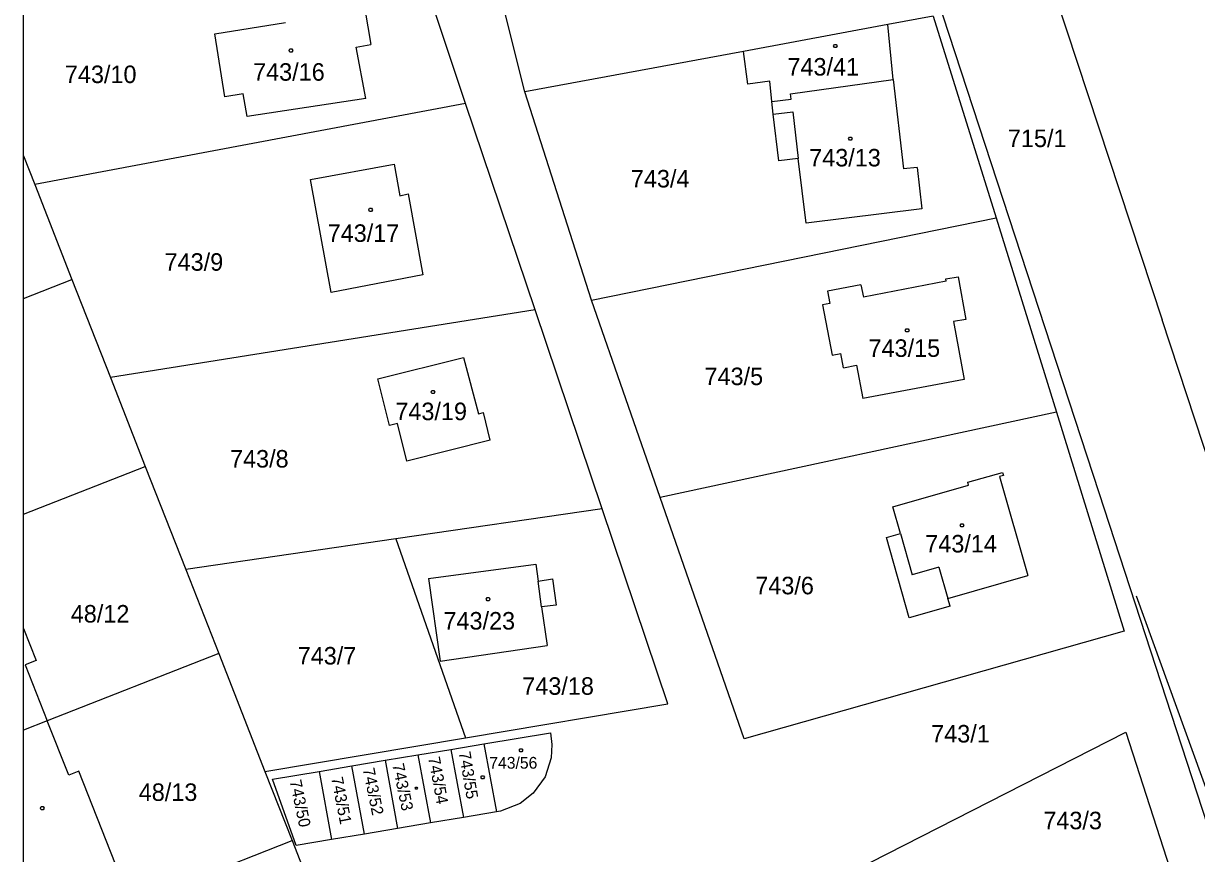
# Model space of a CAD drawing. Extents: x -639590 to -639298, y -1193269 to -1192863.
# Drawn here: x -639590.4 to -639476.5, y -1193132.4 to -1193051.8 of the extents above; entities that cross this region are included whole.
import ezdxf

# ---------------------------------------------------------------- set-up
doc = ezdxf.new("R2010")
doc.units = 0
for name, color, linetype in [('Vrstva 1', 7, 'Continuous'), ('Vrstva 2', 7, 'Continuous'), ('Vrstva 22', 7, 'Continuous'), ('Vrstva 4', 7, 'Continuous'), ('Vrstva 5', 7, 'Continuous'), ('Vrstva 61', 7, 'Continuous')]:
    doc.layers.add(name, color=color, linetype=linetype)

msp = doc.modelspace()

# ---------------------------------------------------------------- linework, layer by layer
at = {"layer": 'Vrstva 1'}
for p, q in [((-639506.87, -1193033.57), (-639486.01, -1193097.33)), ((-639547.47, -1193059.58), (-639554.02, -1193040.01)), ((-639541.72, -1193058.45), (-639545.4, -1193043.83)), ((-639492.18, -1193043.2), (-639479.86, -1193080.55)), ((-639557.26, -1193050.41), (-639556.66, -1193053.85)), ((-639571.83, -1193052.82), (-639564.97, -1193051.71)), ((-639506.48, -1193051.9), (-639520.51, -1193054.51)), ((-639502.09, -1193051.09), (-639506.48, -1193051.9)), ((-639505.97, -1193057.23), (-639506.48, -1193051.9)), ((-639502.09, -1193051.09), (-639495.98, -1193070.66)), ((-639570.85, -1193058.91), (-639571.83, -1193052.82)), ((-639558.11, -1193054.1), (-639556.66, -1193053.85)), ((-639557.17, -1193059.07), (-639558.11, -1193054.1)), ((-639520.51, -1193054.51), (-639541.72, -1193058.45)), ((-639520.08, -1193057.71), (-639520.51, -1193054.51)), ((-639517.95, -1193057.42), (-639520.08, -1193057.71)), ((-639517.76, -1193059.39), (-639517.95, -1193057.42)), ((-639515.93, -1193058.62), (-639505.97, -1193057.23)), ((-639505.97, -1193057.23), (-639504.97, -1193065.92)), ((-639569.05, -1193058.62), (-639570.85, -1193058.91)), ((-639568.69, -1193060.84), (-639569.05, -1193058.62)), ((-639535.24, -1193078.67), (-639541.72, -1193058.45)), ((-639515.86, -1193059.16), (-639515.93, -1193058.62)), ((-639547.47, -1193059.58), (-639589.3, -1193067.44)), ((-639557.17, -1193059.07), (-639568.69, -1193060.84)), ((-639540.73, -1193079.59), (-639547.47, -1193059.58)), ((-639517.76, -1193059.39), (-639515.86, -1193059.16)), ((-639517.61, -1193060.62), (-639517.76, -1193059.39)), ((-639517.08, -1193065.13), (-639517.61, -1193060.62)), ((-639590.39, -1193064.66), (-639589.3, -1193067.44)), ((-639562.54, -1193066.96), (-639554.39, -1193065.47)), ((-639554.39, -1193065.47), (-639553.85, -1193068.54)), ((-639515.18, -1193064.91), (-639517.08, -1193065.13)), ((-639514.42, -1193071.19), (-639515.18, -1193064.91)), ((-639503.63, -1193065.77), (-639504.97, -1193065.92)), ((-639503.63, -1193065.77), (-639503.17, -1193069.78)), ((-639589.3, -1193067.44), (-639585.69, -1193076.64)), ((-639560.52, -1193077.92), (-639562.54, -1193066.96)), ((-639553.85, -1193068.54), (-639553.06, -1193068.33)), ((-639553.06, -1193068.33), (-639551.62, -1193076.2)), ((-639503.17, -1193069.78), (-639514.42, -1193071.19)), ((-639535.24, -1193078.67), (-639495.98, -1193070.66)), ((-639495.98, -1193070.66), (-639490.12, -1193089.51)), ((-639590.39, -1193078.48), (-639585.69, -1193076.64)), ((-639585.69, -1193076.64), (-639581.95, -1193086.16)), ((-639551.62, -1193076.2), (-639560.52, -1193077.92)), ((-639500.81, -1193076.8), (-639508.86, -1193078.35)), ((-639500.85, -1193076.6), (-639499.66, -1193076.39)), ((-639500.81, -1193076.8), (-639500.85, -1193076.6)), ((-639499.66, -1193076.39), (-639498.92, -1193080.53)), ((-639509.09, -1193077.16), (-639512.35, -1193077.79)), ((-639512.35, -1193077.79), (-639512.12, -1193078.98)), ((-639509.09, -1193077.16), (-639508.86, -1193078.35)), ((-639528.59, -1193097.82), (-639535.24, -1193078.67)), ((-639512.12, -1193078.98), (-639512.82, -1193079.11)), ((-639512.82, -1193079.11), (-639511.88, -1193083.98)), ((-639540.73, -1193079.59), (-639581.95, -1193086.16)), ((-639534.22, -1193098.9), (-639540.73, -1193079.59)), ((-639498.92, -1193080.53), (-639500.1, -1193080.74)), ((-639500.1, -1193080.74), (-639499.09, -1193086.35)), ((-639475.06, -1193095.11), (-639479.86, -1193080.55)), ((-639511.88, -1193083.98), (-639511.05, -1193083.82)), ((-639510.78, -1193085.21), (-639511.05, -1193083.82)), ((-639555.99, -1193086.3), (-639547.67, -1193084.22)), ((-639547.67, -1193084.22), (-639546.23, -1193089.69)), ((-639510.78, -1193085.21), (-639509.54, -1193084.97)), ((-639509.54, -1193084.97), (-639508.92, -1193088.21)), ((-639581.95, -1193086.16), (-639578.57, -1193094.79)), ((-639554.86, -1193090.83), (-639555.99, -1193086.3)), ((-639499.09, -1193086.35), (-639508.92, -1193088.21)), ((-639546.23, -1193089.69), (-639545.74, -1193089.57)), ((-639545.08, -1193092.25), (-639545.74, -1193089.57)), ((-639490.12, -1193089.51), (-639528.59, -1193097.82)), ((-639490.12, -1193089.51), (-639483.53, -1193110.77)), ((-639554.09, -1193090.64), (-639554.86, -1193090.83)), ((-639553.18, -1193094.27), (-639554.09, -1193090.64)), ((-639545.08, -1193092.25), (-639553.18, -1193094.27)), ((-639590.39, -1193099.43), (-639578.57, -1193094.79)), ((-639578.57, -1193094.79), (-639574.64, -1193104.8)), ((-639498.72, -1193096.33), (-639495.35, -1193095.38)), ((-639498.64, -1193096.62), (-639498.72, -1193096.33)), ((-639495.27, -1193095.66), (-639495.66, -1193095.77)), ((-639495.66, -1193095.77), (-639492.91, -1193105.39)), ((-639495.35, -1193095.38), (-639495.27, -1193095.66)), ((-639506, -1193098.71), (-639498.64, -1193096.62)), ((-639486.01, -1193097.33), (-639448.4, -1193212.6)), ((-639520.42, -1193121.23), (-639528.59, -1193097.82)), ((-639505.26, -1193101.31), (-639506, -1193098.71)), ((-639534.22, -1193098.9), (-639554.24, -1193101.82)), ((-639527.84, -1193117.84), (-639534.22, -1193098.9)), ((-639554.24, -1193101.82), (-639574.64, -1193104.8)), ((-639554.24, -1193101.82), (-639547.48, -1193121.13)), ((-639506.61, -1193101.69), (-639505.26, -1193101.31)), ((-639504.4, -1193109.48), (-639506.61, -1193101.69)), ((-639551.08, -1193105.65), (-639540.67, -1193104.28)), ((-639540.67, -1193104.28), (-639540.44, -1193105.91)), ((-639574.64, -1193104.8), (-639571.44, -1193112.95)), ((-639500.65, -1193107.6), (-639492.91, -1193105.39)), ((-639551.08, -1193105.65), (-639549.93, -1193113.68)), ((-639540.44, -1193105.91), (-639539.03, -1193105.71)), ((-639539.03, -1193105.71), (-639538.67, -1193108.24)), ((-639500.43, -1193108.36), (-639500.65, -1193107.6)), ((-639538.67, -1193108.24), (-639540.09, -1193108.43)), ((-639540.09, -1193108.43), (-639539.57, -1193112.18)), ((-639500.43, -1193108.36), (-639504.4, -1193109.48)), ((-639590.39, -1193110.53), (-639589.17, -1193113.63)), ((-639483.53, -1193110.77), (-639520.42, -1193121.23)), ((-639549.93, -1193113.68), (-639539.57, -1193112.18)), ((-639571.44, -1193112.95), (-639588.08, -1193119.47)), ((-639571.44, -1193112.95), (-639566.95, -1193124.39)), ((-639589.17, -1193113.63), (-639590.23, -1193114.05)), ((-639590.23, -1193114.05), (-639588.08, -1193119.47)), ((-639547.48, -1193121.13), (-639527.84, -1193117.84)), ((-639588.08, -1193119.47), (-639590.39, -1193120.38)), ((-639585.99, -1193124.74), (-639588.08, -1193119.47)), ((-639566.95, -1193124.39), (-639547.48, -1193121.13)), ((-639554.34, -1193156.7), (-639483.37, -1193120.58)), ((-639545.71, -1193121.71), (-639539.23, -1193120.63)), ((-639539.23, -1193120.63), (-639539.09, -1193121.76)), ((-639483.37, -1193120.58), (-639453.06, -1193214.27)), ((-639552.12, -1193122.78), (-639548.91, -1193122.25)), ((-639548.91, -1193122.25), (-639545.71, -1193121.71)), ((-639548.91, -1193122.25), (-639547.69, -1193128.85)), ((-639545.71, -1193121.71), (-639544.48, -1193128.31)), ((-639539.09, -1193121.76), (-639539.16, -1193123.08)), ((-639558.5, -1193123.85), (-639555.29, -1193123.31)), ((-639555.29, -1193123.31), (-639552.12, -1193122.78)), ((-639555.29, -1193123.31), (-639554.07, -1193129.92)), ((-639552.12, -1193122.78), (-639550.89, -1193129.39)), ((-639539.16, -1193123.08), (-639539.76, -1193124.9)), ((-639585, -1193124.36), (-639585.99, -1193124.74)), ((-639581.47, -1193133.39), (-639585, -1193124.36)), ((-639566.95, -1193124.39), (-639564.32, -1193131.1)), ((-639566.22, -1193125.14), (-639561.7, -1193124.39)), ((-639561.7, -1193124.39), (-639558.5, -1193123.85)), ((-639561.7, -1193124.39), (-639560.48, -1193131)), ((-639557.27, -1193130.46), (-639558.5, -1193123.85)), ((-639539.76, -1193124.9), (-639540.92, -1193126.5)), ((-639563.93, -1193131.58), (-639566.22, -1193125.14)), ((-639540.92, -1193126.5), (-639542.16, -1193127.49)), ((-639544.48, -1193128.31), (-639547.69, -1193128.85)), ((-639544.1, -1193128.25), (-639544.48, -1193128.31)), ((-639542.16, -1193127.49), (-639544.1, -1193128.25)), ((-639550.89, -1193129.39), (-639554.07, -1193129.92)), ((-639547.69, -1193128.85), (-639550.89, -1193129.39)), ((-639557.27, -1193130.46), (-639560.48, -1193131)), ((-639554.07, -1193129.92), (-639557.27, -1193130.46)), ((-639590.39, -1193141.32), (-639564.32, -1193131.1)), ((-639564.32, -1193131.1), (-639557.8, -1193147.72)), ((-639560.48, -1193131), (-639563.93, -1193131.58))]:
    msp.add_line(p, q, dxfattribs=at)
at = {"layer": 'Vrstva 22'}
msp.add_lwpolyline([(-639450.45, -1193202.7), (-639464.28, -1193158.66), (-639472.09, -1193135.67), (-639482.36, -1193107.37)], dxfattribs=at)
at = {"layer": 'Vrstva 4'}
for p, q in [((-639517.61, -1193060.62), (-639515.71, -1193060.39)), ((-639515.71, -1193060.39), (-639515.18, -1193064.91)), ((-639505.26, -1193101.31), (-639504.12, -1193105.3)), ((-639501.53, -1193104.56), (-639504.12, -1193105.3)), ((-639501.53, -1193104.56), (-639500.65, -1193107.6)), ((-639540.09, -1193108.43), (-639540.44, -1193105.91))]:
    msp.add_line(p, q, dxfattribs=at)
at = {"layer": 'Vrstva 5'}
for points in [[(-639564.34, -1193054.28), (-639564.25, -1193054.43), (-639564.34, -1193054.58), (-639564.52, -1193054.58), (-639564.61, -1193054.43), (-639564.52, -1193054.28)], [(-639511.49, -1193053.83), (-639511.4, -1193053.98), (-639511.49, -1193054.13), (-639511.67, -1193054.13), (-639511.76, -1193053.98), (-639511.67, -1193053.83)], [(-639510.03, -1193062.83), (-639509.94, -1193062.98), (-639510.03, -1193063.13), (-639510.21, -1193063.13), (-639510.3, -1193062.98), (-639510.21, -1193062.83)], [(-639556.61, -1193069.74), (-639556.52, -1193069.89), (-639556.61, -1193070.04), (-639556.79, -1193070.04), (-639556.88, -1193069.89), (-639556.79, -1193069.74)], [(-639504.52, -1193081.44), (-639504.43, -1193081.59), (-639504.52, -1193081.74), (-639504.7, -1193081.74), (-639504.79, -1193081.59), (-639504.7, -1193081.44)], [(-639550.56, -1193087.42), (-639550.47, -1193087.57), (-639550.56, -1193087.72), (-639550.74, -1193087.72), (-639550.83, -1193087.57), (-639550.74, -1193087.42)], [(-639499.19, -1193100.36), (-639499.1, -1193100.51), (-639499.19, -1193100.66), (-639499.37, -1193100.66), (-639499.46, -1193100.51), (-639499.37, -1193100.36)], [(-639545.2, -1193107.52), (-639545.11, -1193107.67), (-639545.2, -1193107.82), (-639545.38, -1193107.82), (-639545.47, -1193107.67), (-639545.38, -1193107.52)], [(-639542, -1193122.18), (-639541.91, -1193122.33), (-639542, -1193122.48), (-639542.18, -1193122.48), (-639542.27, -1193122.33), (-639542.18, -1193122.18)], [(-639545.73, -1193124.81), (-639545.64, -1193124.96), (-639545.73, -1193125.11), (-639545.91, -1193125.11), (-639546, -1193124.96), (-639545.91, -1193124.81)], [(-639552.19, -1193125.91), (-639552.13, -1193126.01), (-639552.19, -1193126.11), (-639552.31, -1193126.11), (-639552.37, -1193126.01), (-639552.31, -1193125.91)], [(-639588.48, -1193127.8), (-639588.39, -1193127.95), (-639588.48, -1193128.1), (-639588.66, -1193128.1), (-639588.75, -1193127.95), (-639588.66, -1193127.8)]]:
    msp.add_lwpolyline(points, close=True, dxfattribs=at)
at = {"layer": 'Vrstva 61'}
msp.add_lwpolyline([(-639590.39, -1193268.77), (-639590.39, -1192863.27)], dxfattribs=at)

# ---------------------------------------------------------------- texts
at = {"layer": 'Vrstva 2'}
for s, height, p in [('743/41', 1.7, (-639516.23, -1193056.86)), ('743/10', 1.7, (-639586.37, -1193057.59)), ('743/16', 1.7, (-639568.1, -1193057.36)), ('715/1', 1.7, (-639494.83, -1193063.8)), ('743/13', 1.7, (-639514.12, -1193065.68)), ('743/4', 1.7, (-639531.43, -1193067.72)), ('743/17', 1.7, (-639560.86, -1193073)), ('743/9', 1.7, (-639576.69, -1193075.8)), ('743/15', 1.7, (-639508.36, -1193084.16)), ('743/5', 1.7, (-639524.28, -1193086.9)), ('743/19', 1.7, (-639554.29, -1193090.3)), ('743/8', 1.7, (-639570.34, -1193094.9)), ('743/14', 1.7, (-639502.85, -1193103.14)), ('743/6', 1.7, (-639519.35, -1193107.2)), ('48/12', 1.7, (-639585.8, -1193109.94)), ('743/23', 1.7, (-639549.62, -1193110.62)), ('743/7', 1.7, (-639563.77, -1193114.01)), ('743/18', 1.7, (-639541.97, -1193116.95)), ('743/1', 1.7, (-639502.28, -1193121.58)), ('743/56', 1.14, (-639545.17, -1193124.12)), ('48/13', 1.7, (-639579.2, -1193127.25)), ('743/3', 1.7, (-639491.39, -1193130))]:
    msp.add_text(s, height=height, dxfattribs=at).set_placement(p)
for s, rotation, p in [('743/55', 279.6607, (-639548.14, -1193122.54)), ('743/53', 281.8379, (-639554.6, -1193123.73)), ('743/54', 280.5201, (-639551.11, -1193123.06)), ('743/51', 281.0931, (-639560.53, -1193125.02)), ('743/52', 281.6088, (-639557.46, -1193124.16)), ('743/50', 281.8952, (-639564.56, -1193125.32))]:
    msp.add_text(s, height=1.14, rotation=rotation, dxfattribs=at).set_placement(p)

doc.saveas('drawing.dxf')
